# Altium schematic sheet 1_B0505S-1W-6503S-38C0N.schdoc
size 289 x 200 mm; Name: default297x210; Symbol: default297x210; Device: default297x210; Date: 2025.07.04; Rev: V1.1; Size: "A4"; Id: /; File: B0505S-1W-6503S-38C0N; Sheet: /; @Page No: 1; @Page Count: 1; @Schematic Name: B0505S-1W-6503S-38C0N; @Project Name: 全桥隔离电源-B0505S-1W-6503S-38C0N; @Board Name: B0505S-1W-6503S-38C0N; @Update Date: 2025-07-04; @Create Time: 13:55:23; @Update Time: 16:14:59; @Page Name: B0505S-1W-6503S-38C0N; @Create Date: 2025-06-24
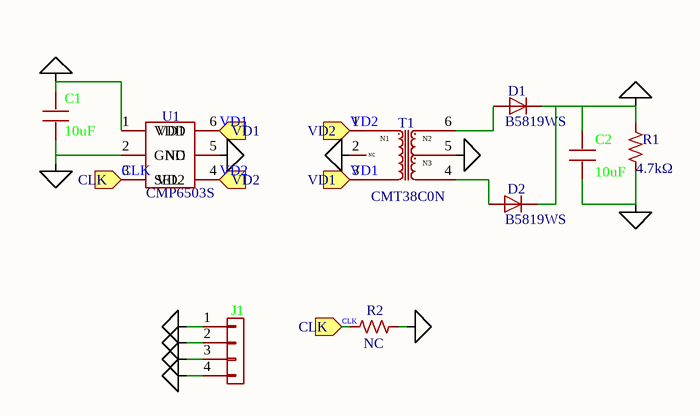
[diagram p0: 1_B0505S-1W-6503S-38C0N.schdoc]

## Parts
C1  10uF  [C0603]
C2  10uF  [C0603]
D1  B5819WS  [SOD-323_L1.8-W1.3-LS2.5-RD]
D2  B5819WS  [SOD-323_L1.8-W1.3-LS2.5-RD]
J1  Connector_Generic_Conn_01x04  [coileasy:PinHeader_01x04_P2.54mm_Vertical]  (value not drawn)
R1  4.7kΩ  [R0603]
R2  NC  [R0603]
T1  CMT38C0N  [coileasy:CMT38xxx]
U1  CMP6503S  [coileasy:SOT-23-6]

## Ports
CLK (in), VD1 (in), VD2 (in)

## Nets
0V: C2.1 J1.3 R1.2 T1.5
+VO: C2.2 D1.1 D2.1 J1.4 R1.1
GND: C1.1 J1.1 R2.2 U1.2(GND)
VIN: C1.2 J1.2 T1.2 U1.1(VDD) U1.5(NC)
CLK: R2.1 U1.3(SEL) ; port CLK
VD1: T1.3 U1.6(VD1) ; port VD1
VD2: T1.1 U1.4(VD2) ; port VD2
NetD1_2: D1.2 T1.6
NetD2_2: D2.2 T1.4

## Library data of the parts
C1 C2 = 0603X106K100NT: Manufacturer: FH(风华); Symbol: My_Library_C; Add into BOM: yes; Tolerance: ±10%; Voltage Rated: 10V; Temperature Coefficient: X5R
D1 D2 = B5819WS_C64886: Manufacturer: MDD(辰达半导体); Symbol: My_Library_D; Add into BOM: yes; Diode Configuration: 独立式; Forward Voltage (Vf@If): 900mV@3A; Reverse Voltage (Vr): 40V; Rectified Current: 1A; Reverse Leakage Current (Ir): 1mA@40V
J1 = Connector_Generic_Conn_01x04: Users: REF**; ki_fp_filters: Connector*:*_1x??_*; Add into BOM: yes
R1 = RC0603FR-074K7L: Manufacturer: YAGEO(国巨); Symbol: R; Add into BOM: yes; Tolerance: ±1%; Power(Watts): 100mW; Overload Voltage (Max): 75V; Temperature Coefficient: ±100ppm/℃
R2 = R: Add into BOM: yes; Tolerance: ±1%; Power(Watts): 100mW; Overload Voltage (Max): 75V; Temperature Coefficient: ±100ppm/℃
T1 = MYLibrary _CMT38xxxx: Users: REF**; Add into BOM: yes
U1 = CMP6503S: Manufacturer: coileasy(线易); Symbol: MYLibrary_CMP6xxxx; Add into BOM: yes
